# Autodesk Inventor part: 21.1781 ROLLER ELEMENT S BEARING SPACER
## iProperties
Created: 2007-05
Part Number: 21.1781 ROLLER ELEMENT S BEARING SPACER
Material: Aluminum-6061
Document SubType Name: Modeling
Designer: Andy Moles
Density: 2.71 g/cm^3
Mass: 3.3017 g
Surface Area: 9.14455 cm^2
Volume: 1.21834 cm^3
Author: Andy Moles
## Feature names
1. Extrusion1
2. Extrusion2
3. Mirror1
